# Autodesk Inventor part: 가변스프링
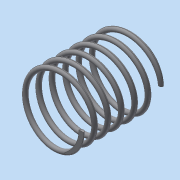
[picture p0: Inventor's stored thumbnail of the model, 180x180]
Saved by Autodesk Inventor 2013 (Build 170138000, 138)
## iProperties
Created: 2018-02
Part Number: 가변스프링
Material: 일반
Document SubType Name: Modeling
Designer: dgall
Density: 1 g/cm^3
Author: dgall
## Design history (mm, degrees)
sketch "스케치1"
  geometry: L1 (20, 0)-(0, 0); L2 (0, 0)-(0, 51.25); L3 (0, 51.25)-(20, 51.25); C1 r 1.5 at (20, 0)
  constraints: 6 end point, 1 centre point, 1 coincident, 1 horizontal, 1 parallel, 1 perpendicular, 1 vertical alignment
  dimensions: "d0" = 51.25 distance of L1.end L2.end (derived); "d2" = 40 diameter of L1.start L2; "d3" = 3 diameter of C1
feature "코일1" sketch "스케치1" pitch "d4" = 10; turns "d6" = 6; dims "d5" = 51.25 (= d0), "d7" = 0, angle "d8" = 90 deg, angle "d9" = 90 deg, "d10" = 0, "d11" = 0
node "작업 평면1"
node "작업 평면2"
feature "분할1"
feature "분할2"
node "솔리드1"
other parameters: "d12" = 0, "d13" = 0
